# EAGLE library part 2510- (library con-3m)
3M (TM) Pak 100 4-Wall Header Source: 3M
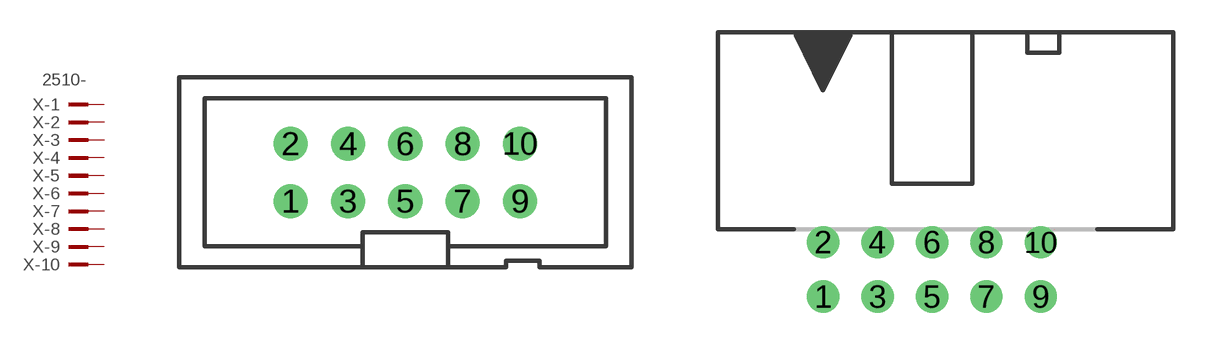
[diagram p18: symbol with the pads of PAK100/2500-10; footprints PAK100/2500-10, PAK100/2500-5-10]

Designator prefix X; gates -1=PINV -2=PIN -3=PIN -4=PIN -5=PIN -6=PIN -7=PIN -8=PIN -9=PIN -10=PIN

## 2510- (MF: 3M; MPN: 2510-6002UB; OC_FARNELL: 9838244; OC_NEWARK: 46F4725)  [PAK100/2500-10]
1  -1:KL  pas
2  -2:KL  pas
3  -3:KL  pas
4  -4:KL  pas
5  -5:KL  pas
6  -6:KL  pas
7  -7:KL  pas
8  -8:KL  pas
9  -9:KL  pas
10  -10:KL  pas

## 2510-5 (OC_FARNELL: 1788669; OC_NEWARK: unknown)  [PAK100/2500-5-10]
Pads as for PAK100/2500-10

## Footprint PAK100/2500-10 (pad centres in mm)
3M (TM) Pak 100 4-Wall Header Straight Source: 3M
drill 1 pad 1.422 round: 1 -5.08,-1.27; 2 -5.08,1.27; 3 -2.54,-1.27; 4 -2.54,1.27; 5 0,-1.27; 6 0,1.27; 7 2.54,-1.27; 8 2.54,1.27; 9 5.08,-1.27; 10 5.08,1.27

## Footprint PAK100/2500-5-10 (pad centres in mm)
3M (TM) Pak 100 4-Wall Header Right Angle Source: 3M
drill 1 pad 1.422 round: 1 -5.08,-1.27; 2 -5.08,1.27; 3 -2.54,-1.27; 4 -2.54,1.27; 5 0,-1.27; 6 0,1.27; 7 2.54,-1.27; 8 2.54,1.27; 9 5.08,-1.27; 10 5.08,1.27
